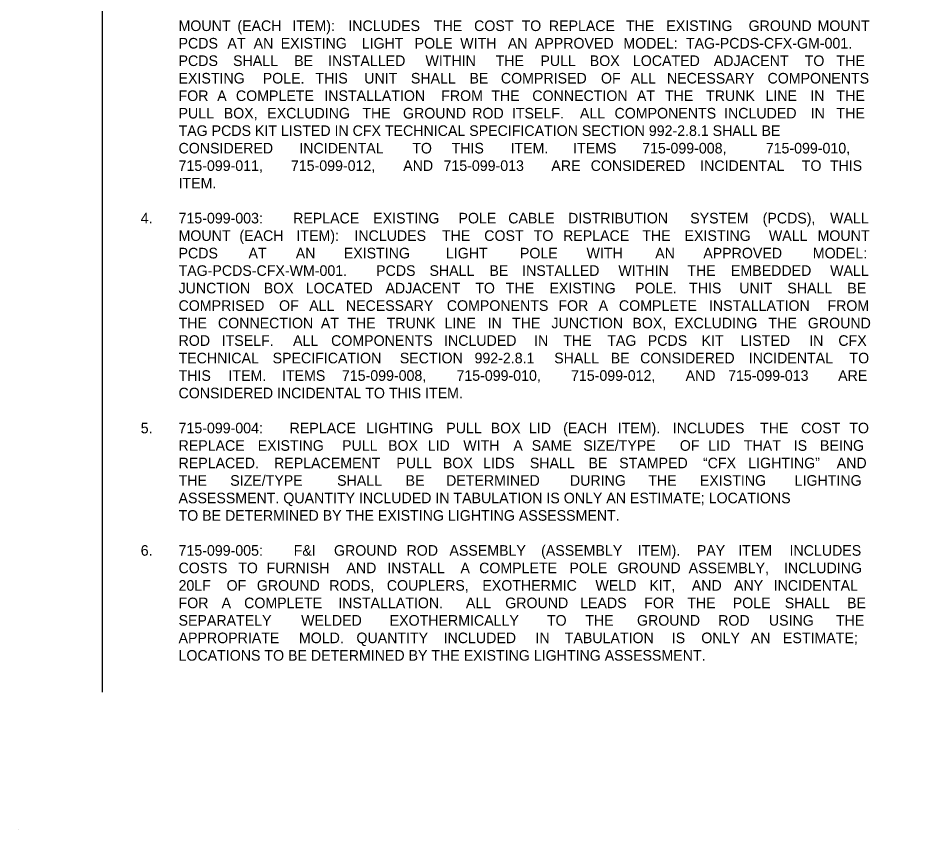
# Model space of a CAD drawing. Extents: x -55 to 2471539, y -90 to 3608906.
# Drawn here: x -55 to 543, y -90 to 440 of the extents above; entities that cross this region are included whole.
import ezdxf

# ---------------------------------------------------------------- set-up
doc = ezdxf.new("R2010")
doc.units = 0
for name, color, linetype in [('AdhocPoint_dp', 7, 'Continuous'), ('NonPlottingEle_dp', 7, 'Continuous'), ('TextNotes', 7, 'Continuous')]:
    doc.layers.add(name, color=color, linetype=linetype)

msp = doc.modelspace()

# ---------------------------------------------------------------- linework, layer by layer
at = {"layer": 'AdhocPoint_dp'}
msp.add_line((-55, -90), (-55, -90), dxfattribs=at)
at = {"layer": 'NonPlottingEle_dp'}
msp.add_lwpolyline([(0, 0), (0, 960), (1540, 960), (1540, 0)], dxfattribs=at)

# ---------------------------------------------------------------- texts
at = {"layer": 'TextNotes'}
for s, p in [('MOUNT ', (49.75, 432.14)), ('(EACH ', (88.2, 432.14)), ('ITEM): ', (124.16, 432.14)), ('INCLUDES ', (160.72, 432.14)), ('THE ', (216.58, 432.14)), ('COST ', (242.95, 432.14)), ('TO ', (273.95, 432.14)), ('REPLACE ', (291.81, 432.14)), ('THE ', (342.23, 432.14)), ('EXISTING ', (368.6, 432.14)), ('GROUND ', (422.37, 432.14)), ('MOUNT ', (467.44, 432.14)), ('PCDS ', (49.75, 420.71)), ('AT ', (81.71, 420.71)), ('AN ', (98.83, 420.71)), ('EXISTING ', (116.5, 420.71)), ('LIGHT ', (169.49, 420.71)), ('POLE ', (204.09, 420.71)), ('WITH ', (233.86, 420.71)), ('AN ', (265, 420.71)), ('APPROVED ', (282.66, 420.71)), ('MODEL: ', (340.5, 420.71)), ('TAG-PCDS-CFX-GM-001. ', (381.42, 420.71)), ('PCDS ', (49.75, 409.27)), ('SHALL ', (85.39, 409.27)), ('BE ', (125.34, 409.27)), ('INSTALLED ', (147.52, 409.27)), ('WITHIN ', (211.16, 409.27)), ('THE ', (257.02, 409.27)), ('PULL ', (286.29, 409.27)), ('BOX ', (318.54, 409.27)), ('LOCATED ', (346.74, 409.27)), ('ADJACENT ', (399.62, 409.27)), ('TO ', (459.04, 409.27)), ('THE ', (479.8, 409.27)), ('EXISTING ', (49.75, 397.84)), ('POLE. ', (104.76, 397.84)), ('THIS ', (139.22, 397.84)), ('UNIT ', (171.15, 397.84)), ('SHALL ', (201.63, 397.84)), ('BE ', (239.92, 397.84)), ('COMPRISED ', (260.45, 397.84)), ('OF ', (325.88, 397.84)), ('ALL ', (345.31, 397.84)), ('NECESSARY ', (369.01, 397.84)), ('COMPONENTS ', (434.75, 397.84)), ('FOR ', (49.75, 386.4)), ('A ', (75.02, 386.4)), ('COMPLETE ', (87.25, 386.4)), ('INSTALLATION ', (145.03, 386.4)), ('FROM ', (221.45, 386.4)), ('THE ', (254.17, 386.4)), ('CONNECTION ', (281, 386.4)), ('AT ', (349.37, 386.4)), ('THE ', (367.73, 386.4)), ('TRUNK ', (394.56, 386.4)), ('LINE ', (433.4, 386.4)), ('IN ', (462.71, 386.4)), ('THE ', (479.8, 386.4)), ('PULL ', (49.75, 374.97)), ('BOX, ', (79.29, 374.97)), ('EXCLUDING ', (107.73, 374.97)), ('THE ', (169.89, 374.97)), ('GROUND ', (196.46, 374.97)), ('ROD ', (241.71, 374.97)), ('ITSELF. ', (267.65, 374.97)), ('ALL ', (312.1, 374.97)), ('COMPONENTS ', (334.74, 374.97)), ('INCLUDED ', (406.35, 374.97)), ('IN ', (462.98, 374.97)), ('THE ', (479.8, 374.97)), ('TAG PCDS KIT LISTED IN CFX TECHNICAL SPECIFICATION SECTION 992-2.8.1 SHALL BE ', (49.75, 363.54)), ('CONSIDERED ', (49.75, 352.1)), ('INCIDENTAL ', (128.7, 352.1)), ('TO ', (202.5, 352.1)), ('THIS ', (228.22, 352.1)), ('ITEM. ', (266.76, 352.1)), ('ITEMS ', (307.69, 352.1)), ('715-099-008, ', (352.78, 352.1)), ('715-099-010, ', (433.6, 352.1)), ('715-099-011, ', (49.75, 340.67)), ('715-099-012, ', (123.18, 340.67)), ('AND ', (196.62, 340.67)), ('715-099-013 ', (222.94, 340.67)), ('ARE ', (293.43, 340.67)), ('CONSIDERED ', (319.17, 340.67)), ('INCIDENTAL ', (390.73, 340.67)), ('TO ', (457.15, 340.67)), ('THIS ', (475.49, 340.67)), ('ITEM.', (49.75, 329.23)), ('4.', (25.02, 306.36)), ('715-099-003: ', (49.75, 306.36)), ('REPLACE ', (124.63, 306.36)), ('EXISTING ', (177.01, 306.36)), ('POLE ', (232.74, 306.36)), ('CABLE ', (265.25, 306.36)), ('DISTRIBUTION ', (304.33, 306.36)), ('SYSTEM ', (384.2, 306.36)), ('(PCDS), ', (431.56, 306.36)), ('WALL ', (475.67, 306.36)), ('MOUNT ', (49.75, 294.93)), ('(EACH ', (89.52, 294.93)), ('ITEM): ', (126.81, 294.93)), ('INCLUDES ', (164.7, 294.93)), ('THE ', (221.87, 294.93)), ('COST ', (249.57, 294.93)), ('TO ', (281.9, 294.93)), ('REPLACE ', (301.08, 294.93)), ('THE ', (352.82, 294.93)), ('EXISTING ', (380.52, 294.93)), ('WALL ', (435.62, 294.93)), ('MOUNT ', (467.44, 294.93)), ('PCDS ', (49.75, 283.49)), ('AT ', (95.47, 283.49)), ('AN ', (126.36, 283.49)), ('EXISTING ', (157.78, 283.49)), ('LIGHT ', (224.53, 283.49)), ('POLE ', (272.9, 283.49)), ('WITH ', (316.43, 283.49)), ('AN ', (361.33, 283.49)), ('APPROVED ', (392.75, 283.49)), ('MODEL: ', (464.35, 283.49)), ('TAG-PCDS-CFX-WM-001. ', (49.75, 272.06)), ('PCDS ', (178.89, 272.06)), ('SHALL ', (213.77, 272.06)), ('BE ', (252.95, 272.06)), ('INSTALLED ', (274.37, 272.06)), ('WITHIN ', (337.24, 272.06)), ('THE ', (382.34, 272.06)), ('EMBEDDED ', (410.85, 272.06)), ('WALL ', (475.67, 272.06)), ('JUNCTION ', (49.75, 260.63)), ('BOX ', (105.43, 260.63)), ('LOCATED ', (132.88, 260.63)), ('ADJACENT ', (185, 260.63)), ('TO ', (243.68, 260.63)), ('THE ', (263.68, 260.63)), ('EXISTING ', (292.21, 260.63)), ('POLE. ', (348.13, 260.63)), ('THIS ', (383.49, 260.63)), ('UNIT ', (416.32, 260.63)), ('SHALL ', (447.7, 260.63)), ('BE ', (486.9, 260.63)), ('COMPRISED ', (49.75, 249.19)), ('OF ', (115.44, 249.19)), ('ALL ', (135.14, 249.19)), ('NECESSARY ', (159.1, 249.19)), ('COMPONENTS ', (225.09, 249.19)), ('FOR ', (298.02, 249.19)), ('A ', (324.35, 249.19)), ('COMPLETE ', (337.61, 249.19)), ('INSTALLATION ', (396.45, 249.19)), ('FROM ', (473.91, 249.19)), ('THE ', (49.75, 237.76)), ('CONNECTION ', (75.49, 237.76)), ('AT ', (142.77, 237.76)), ('THE ', (160.05, 237.76)), ('TRUNK ', (185.79, 237.76)), ('LINE ', (223.54, 237.76)), ('IN ', (251.76, 237.76)), ('THE ', (267.76, 237.76)), ('JUNCTION ', (293.51, 237.76)), ('BOX, ', (346.4, 237.76)), ('EXCLUDING ', (374.02, 237.76)), ('THE ', (435.36, 237.76)), ('GROUND ', (461.11, 237.76)), ('ROD ', (49.75, 226.32)), ('ITSELF. ', (77.92, 226.32)), ('ALL ', (124.59, 226.32)), ('COMPONENTS ', (149.46, 226.32)), ('INCLUDED ', (223.3, 226.32)), ('IN ', (282.15, 226.32)), ('THE ', (301.2, 226.32)), ('TAG ', (329.99, 226.32)), ('PCDS ', (356.48, 226.32)), ('KIT ', (391.64, 226.32)), ('LISTED ', (417.04, 226.32)), ('IN ', (461.99, 226.32)), ('CFX ', (481.03, 226.32)), ('TECHNICAL ', (49.75, 214.89)), ('SPECIFICATION ', (111.24, 214.89)), ('SECTION ', (194.38, 214.89)), ('992-2.8.1 ', (243.21, 214.89)), ('SHALL ', (295.31, 214.89)), ('BE ', (332.27, 214.89)), ('CONSIDERED ', (351.46, 214.89)), ('INCIDENTAL ', (422.46, 214.89)), ('TO ', (488.31, 214.89)), ('THIS ', (49.75, 203.45)), ('ITEM. ', (82.37, 203.45)), ('ITEMS ', (117.37, 203.45)), ('715-099-008, ', (156.53, 203.45)), ('715-099-010, ', (231.42, 203.45)), ('715-099-012, ', (306.31, 203.45)), ('AND ', (381.19, 203.45)), ('715-099-013 ', (408.98, 203.45)), ('ARE ', (480.91, 203.45)), ('CONSIDERED INCIDENTAL TO THIS ITEM.', (49.75, 192.02)), ('5.', (25.02, 169.15)), ('715-099-004: ', (49.75, 169.15)), ('REPLACE ', (122.36, 169.15)), ('LIGHTING ', (172.46, 169.15)), ('PULL ', (224.76, 169.15)), ('BOX ', (253.79, 169.15)), ('LID ', (278.78, 169.15)), ('(EACH ', (301.17, 169.15)), ('ITEM). ', (336.82, 169.15)), ('INCLUDES ', (372.81, 169.15)), ('THE ', (429.88, 169.15)), ('COST ', (456.65, 169.15)), ('TO ', (488.18, 169.15)), ('REPLACE ', (49.75, 157.71)), ('EXISTING ', (101.47, 157.71)), ('PULL ', (156.65, 157.71)), ('BOX ', (186.72, 157.71)), ('LID ', (212.64, 157.71)), ('WITH ', (235.88, 157.71)), ('A ', (268.59, 157.71)), ('SAME ', (280.6, 157.71)), ('SIZE/TYPE ', (314.32, 157.71)), ('OF ', (377.41, 157.71)), ('LID ', (396.02, 157.71)), ('THAT ', (419.26, 157.71)), ('IS ', (451.88, 157.71)), ('BEING ', (469.03, 157.71)), ('REPLACED. ', (49.75, 146.28)), ('REPLACEMENT ', (112.15, 146.28)), ('PULL ', (192.11, 146.28)), ('BOX ', (222.53, 146.28)), ('LIDS ', (248.79, 146.28)), ('SHALL ', (279.38, 146.28)), ('BE ', (317.71, 146.28)), ('STAMPED ', (337.78, 146.28)), ('“CFX ', (392.56, 146.28)), ('LIGHTING” ', (422.15, 146.28)), ('AND ', (479.97, 146.28)), ('THE ', (49.75, 134.85)), ('SIZE/TYPE ', (83.53, 134.85)), ('SHALL ', (153.39, 134.85)), ('BE ', (198.14, 134.85)), ('DETERMINED ', (224.63, 134.85)), ('DURING ', (305.58, 134.85)), ('THE ', (356.76, 134.85)), ('EXISTING ', (390.54, 134.85)), ('LIGHTING ', (452.48, 134.85)), ('ASSESSMENT. QUANTITY INCLUDED IN TABULATION IS ONLY AN ESTIMATE; LOCATIONS ', (49.75, 123.41)), ('TO BE DETERMINED BY THE EXISTING LIGHTING ASSESSMENT.', (49.75, 111.98)), ('6.', (25.02, 89.11)), ('715-099-005: ', (49.75, 89.11)), ('F&I ', (125, 89.11)), ('GROUND ', (151.36, 89.11)), ('ROD ', (198.75, 89.11)), ('ASSEMBLY ', (226.82, 89.11)), ('(ASSEMBLY ', (286.75, 89.11)), ('ITEM). ', (349.9, 89.11)), ('PAY ', (388.52, 89.11)), ('ITEM ', (415.58, 89.11)), ('INCLUDES ', (449.13, 89.11)), ('COSTS ', (49.75, 77.67)), ('TO ', (88.73, 77.67)), ('FURNISH ', (107.19, 77.67)), ('AND ', (159.49, 77.67)), ('INSTALL ', (186.17, 77.67)), ('A ', (234.02, 77.67)), ('COMPLETE ', (246.22, 77.67)), ('POLE ', (305.25, 77.67)), ('GROUND ', (336.75, 77.67)), ('ASSEMBLY, ', (383.18, 77.67)), ('INCLUDING ', (445.51, 77.67)), ('20LF ', (49.75, 66.24)), ('OF ', (81.15, 66.24)), ('GROUND ', (100.92, 66.24)), ('RODS, ', (148.3, 66.24)), ('COUPLERS, ', (185.88, 66.24)), ('EXOTHERMIC ', (248.33, 66.24)), ('WELD ', (322.26, 66.24)), ('KIT, ', (357.51, 66.24)), ('AND ', (385.23, 66.24)), ('ANY ', (412.86, 66.24)), ('INCIDENTAL ', (438.77, 66.24)), ('FOR ', (49.75, 54.8)), ('A ', (77.88, 54.8)), ('COMPLETE ', (92.61, 54.8)), ('INSTALLATION. ', (154.15, 54.8)), ('ALL ', (237.58, 54.8)), ('GROUND ', (263.29, 54.8)), ('LEADS ', (312.24, 54.8)), ('FOR ', (354.13, 54.8)), ('THE ', (382.27, 54.8)), ('POLE ', (412, 54.8)), ('SHALL ', (446.03, 54.8)), ('BE ', (486.73, 54.8)), ('SEPARATELY ', (49.75, 43.37)), (' WELDED ', (127.32, 43.37)), ('EXOTHERMICALLY ', (187.75, 43.37)), ('TO ', (290.53, 43.37)), ('THE ', (315.61, 43.37)), ('GROUND ', (349.42, 43.37)), ('ROD ', (402.46, 43.37)), ('USING ', (435.64, 43.37)), ('THE ', (479.44, 43.37)), ('APPROPRIATE ', (49.75, 31.94)), ('MOLD. ', (128.43, 31.94)), ('QUANTITY ', (166.03, 31.94)), ('INCLUDED ', (222.99, 31.94)), ('IN ', (283.06, 31.94)), ('TABULATION ', (302.22, 31.94)), ('IS ', (372.16, 31.94)), ('ONLY ', (391.46, 31.94)), ('AN ', (423.81, 31.94)), ('ESTIMATE; ', (444.84, 31.94)), ('LOCATIONS TO BE DETERMINED BY THE EXISTING LIGHTING ASSESSMENT.', (49.75, 20.5))]:
    msp.add_text(s, height=6.93, dxfattribs=at).set_placement(p)

doc.saveas('drawing.dxf')
